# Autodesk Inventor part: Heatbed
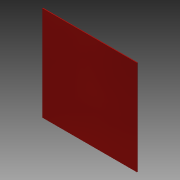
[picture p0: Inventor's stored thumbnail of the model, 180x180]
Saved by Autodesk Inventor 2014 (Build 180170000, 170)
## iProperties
Created: 2013-12
Part Number: Heatbed
Material: Aluminum, Anodized Red
Document SubType Name: Modeling
Designer: Bram
Density: 2.71 g/cm^3
Appearance: Anodized - Red
Author: Bram
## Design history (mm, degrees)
sketch "Sketch1"
  geometry: L1 (-107, 107)-(107, 107); L2 (107, 107)-(107, -107); L3 (107, -107)-(-107, -107); L4 (-107, -107)-(-107, 107); L5 (-107, 107)-(107, -107); L6 (107, 107)-(-107, -107); 1 further point
  constraints: 12 end point, 2 midpoint, 2 parallel, 1 horizontal, 1 perpendicular
  dimensions: "d0" = 214 distance of L2.end L3.end; "d1" = 214 distance of L1.end L2.end
extrude "Extrusion1" new body sketch "Sketch1" distance "d2" = 1.6; taper "d3" = 0 deg
sketch "Sketch2"
  geometry: L1 (-107, 107)-(-107, -107) reference; L2 (0, 13.991)-(-10, -3.329); L3 (0, 13.991)-(20, 13.991); L4 (-10, -3.329)-(10, -3.329); L5 (10, -3.329)-(0, 13.991); L6 (-5.403, 2.733)-(4.932, 2.733); L7 (4.932, 2.733)-(4.932, -0.915); L8 (4.932, -0.915)-(-5.403, -0.915); L9 (-5.403, -0.915)-(-5.403, 2.733); L10 (12.242, -5.054)-(0.072, 16.026); L11 (0.072, 16.026)-(-12.098, -5.054); L12 (-12.098, -5.054)-(12.242, -5.054); 1 further point
  constraints: 14 end point, 1 equal length, 1 horizontal, 1 perpendicular, 2 other
  dimensions: "d4" = 20 distance of L2.start L2.end; "d6" = 20 distance of L2.end L4.end; "d9" = 24.34 distance of L10.end L11.end; "d10" = 24.34 distance of L11.end L10.start
extrude "Extrusion2" join sketch "Sketch2" distance "d11" = 0.1; taper "d12" = 0 deg
body "Solid1"
